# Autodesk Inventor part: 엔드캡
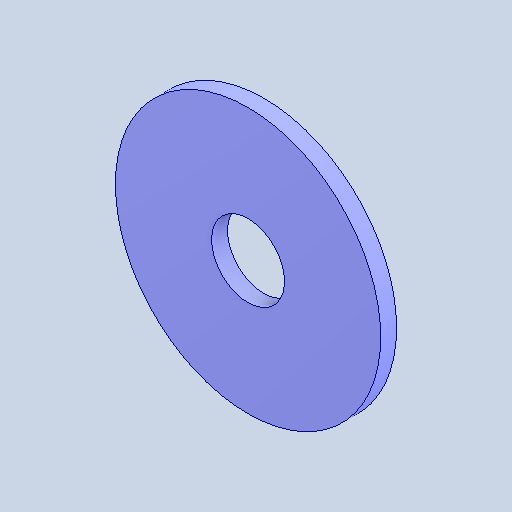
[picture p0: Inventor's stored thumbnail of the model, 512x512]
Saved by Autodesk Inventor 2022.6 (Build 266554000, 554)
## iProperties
Created: 2024-09
Part Number: 엔드캡
Material: 강철, 연강
Document SubType Name: Modeling
Designer: Class 001
Density: 7.85 g/cm^3
Appearance: 기본값
Author: jhkim
Sending System: Autodesk Inventor 2025
Preprocessor: ST-DEVELOPER v20
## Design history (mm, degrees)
feature "솔리드1"
node "솔리드2"
